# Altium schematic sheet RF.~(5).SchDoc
size A3
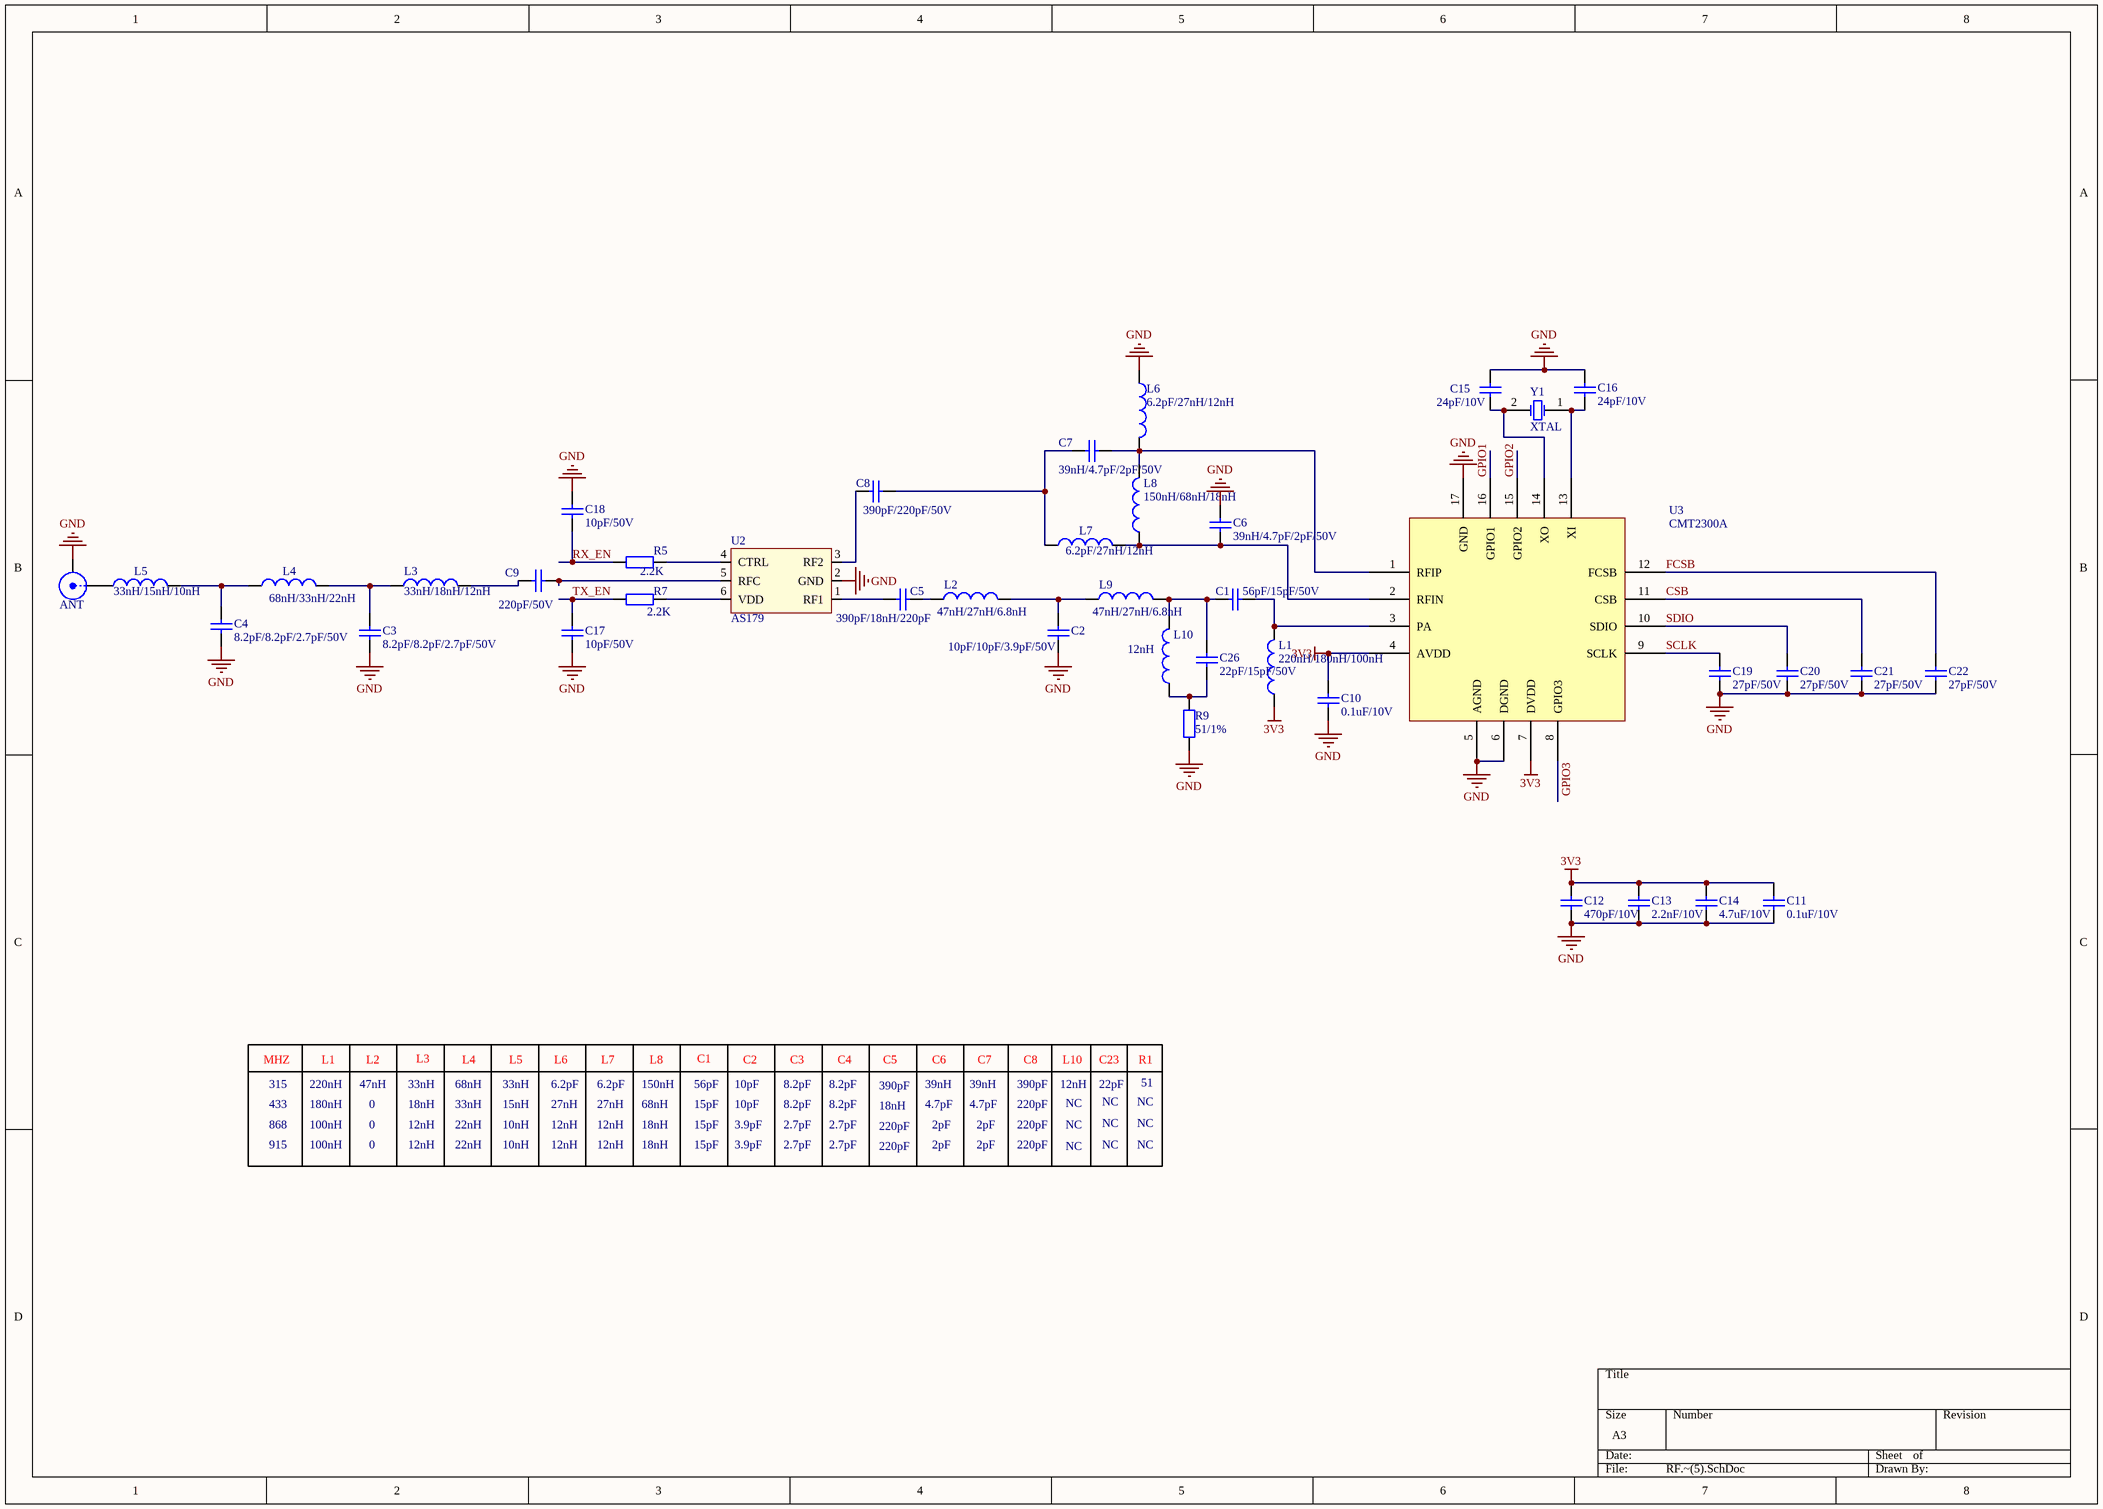
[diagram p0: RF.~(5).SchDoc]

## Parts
ANT  (no value)  [SMA Straight SMD]
C1  56pF/15pF/50V  [0603C]
C2  10pF/10pF/3.9pF/50V  [0603C]
C3  8.2pF/8.2pF/2.7pF/50V  [0603C]
C4  8.2pF/8.2pF/2.7pF/50V  [0603C]
C5  390pF/18nH/220pF  [0603C]
C6  39nH/4.7pF/2pF/50V  [0603C]
C7  39nH/4.7pF/2pF/50V  [0603C]
C8  390pF/220pF/50V  [0603C]
C9  220pF/50V  [0603C]
C10  0.1uF/10V  [0603C]
C11  0.1uF/10V  [0603C]
C12  470pF/10V  [0603C]
C13  2.2nF/10V  [0603C]
C14  4.7uF/10V  [0603C]
C15  24pF/10V  [0603C]
C16  24pF/10V  [0603C]
C17  10pF/50V  [0603C]
C18  10pF/50V  [0603C]
C19  27pF/50V  [0603C]
C20  27pF/50V  [0603C]
C21  27pF/50V  [0603C]
C22  27pF/50V  [0603C]
C26  22pF/15pF/50V  [0603C]
L1  220nH/180nH/100nH  [0603R]
L2  47nH/27nH/6.8nH  [0603R]
L3  33nH/18nH/12nH  [0603R]
L4  68nH/33nH/22nH  [0603R]
L5  33nH/15nH/10nH  [0603R]
L6  6.2pF/27nH/12nH  [0603R]
L7  6.2pF/27nH/12nH  [0603R]
L8  150nH/68nH/18nH  [0603R]
L9  47nH/27nH/6.8nH  [0603R]
L10  12nH  [0603R]
R5  2.2K  [0603R]
R7  2.2K  [0603R]
R9  51/1%  [0603R]
U2  AS179
U3  CMT2300A
Y1  XTAL  [BCY-W2/D3.1]

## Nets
3V3: C10.1 C11.1 C12.1 C13.1 C14.1 L1.1 U3.4(AVDD) U3.7(DVDD)
GND: ANT.2(GND) C2.1 C3.2 C4.2 C6.2 C10.2 C11.2 C12.2 C13.2 C14.2 C15.1 C16.1 C17.1 C18.2 C19.2 C20.2 C21.2 C22.2 L6.1 R9.2 U2.2(GND) U3.5(AGND) U3.6(DGND) U3.17(GND)
CSB: C21.1 U3.11(CSB)
FCSB: C22.1 U3.12(FCSB)
GPIO1: U3.16(GPIO1)
GPIO2: U3.15(GPIO2)
GPIO3: U3.8(GPIO3)
RX_EN: C18.1 R5.2
SCLK: C19.1 U3.9(SCLK)
SDIO: C20.1 U3.10(SDIO)
TX_EN: C17.2 R7.2
NetANT_1: ANT.1(Signal) L5.1
NetC1_1: C1.1 C26.2 L9.2 L10.2
NetC1_2: C1.2 L1.2 U3.3(PA)
NetC2_2: C2.2 L2.2 L9.1
NetC3_1: C3.1 L3.1 L4.2
NetC4_1: C4.1 L4.1 L5.2
NetC5_1: C5.1 U2.1(RF1)
NetC5_2: C5.2 L2.1
NetC6_1: C6.1 L7.2 L8.1 U3.2(RFIN)
NetC7_1: C7.1 C8.2 L7.1
NetC7_2: C7.2 L6.2 L8.2 U3.1(RFIP)
NetC8_1: C8.1 U2.3(RF2)
NetC9_1: C9.1 U2.5(RFC)
NetC9_2: C9.2 L3.2
NetC15_2: C15.2 U3.14(XO) Y1.2(OSC2)
NetC16_2: C16.2 U3.13(XI) Y1.1(OSC1)
NetC26_1: C26.1 L10.1 R9.1
NetR5_1: R5.1 U2.4(CTRL)
NetR7_1: R7.1 U2.6(VDD)

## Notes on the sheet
- MHZ
- 315
- 433
- 868
- 220nH
- 180nH
- 100nH
- L1
- 47nH
- L2
- 0
- 33nH
- 18nH
- 12nH
- L3
- 68nH
- 22nH
- L4
- 15nH
- 10nH
- L5
- 6.2pF
- 27nH
- L6
- L7
- 150nH
- L8
- 56pF
- 15pF
- C1
- 10pF
- 3.9pF
- C2
- 8.2pF
- 2.7pF
- C3
- C4
- 390pF
- C5
- 39nH
- 4.7pF
- C6
- 2pF
- C7
- 220pF
- C8
- L10
- NC
- C23
- 22pF
- R1
- 51
- 915

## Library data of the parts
ANT = SMA: SMA Straight Connector
C1-C22 C26 = Cap: Capacitor; Value: 106
L1-L10 = Inductor: Code_IEC: 1005; Value: 10mH
R5 R7 R9 = Res2: Resistor; Value: 10K/5%/1/8W
U2 = PE4259 RF Switch: PE4259 Peregrine RF Switch
Y1 = XTAL: Crystal Oscillator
